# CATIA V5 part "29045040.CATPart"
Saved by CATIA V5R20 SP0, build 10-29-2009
Part number: 29045040
Definition: NONE
Nomenclature: 29045040
Source: Unknown
Description: 29045040
Bounding box of the stored display mesh (mm): x -20 to 44.548, y -36.5 to 71.048, z -26.5 to 26.5
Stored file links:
  C:\Users\Utente\Desktop\IO LAVORO\3D X SITO CF\X SITO\PLASTICA\RF1\29045040.CATPart
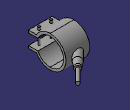
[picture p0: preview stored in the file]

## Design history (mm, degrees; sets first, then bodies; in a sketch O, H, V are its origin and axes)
Body1 "29045040" (main body)
  Solid1: solid without history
